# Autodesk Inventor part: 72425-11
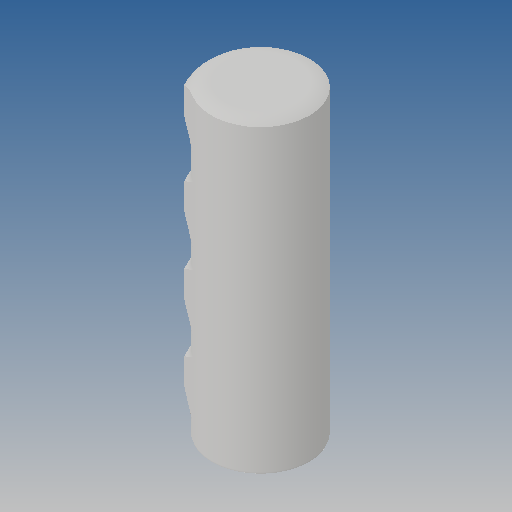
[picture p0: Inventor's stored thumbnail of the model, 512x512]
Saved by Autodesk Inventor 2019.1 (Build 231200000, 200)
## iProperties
Created: 2012-10
Part Number: 72425-11
Material: Ogólny
Document SubType Name: Modeling
Designer: CADENGINEERING4
Density: 1 g/cm^3
Appearance: Domyślna
Author: CADENGINEERING4
Revision Number: ÈÎºÎ
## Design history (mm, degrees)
feature "ÊäÈë1"
node "Bryła1"
